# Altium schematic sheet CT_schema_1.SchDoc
size 514 x 469 mm
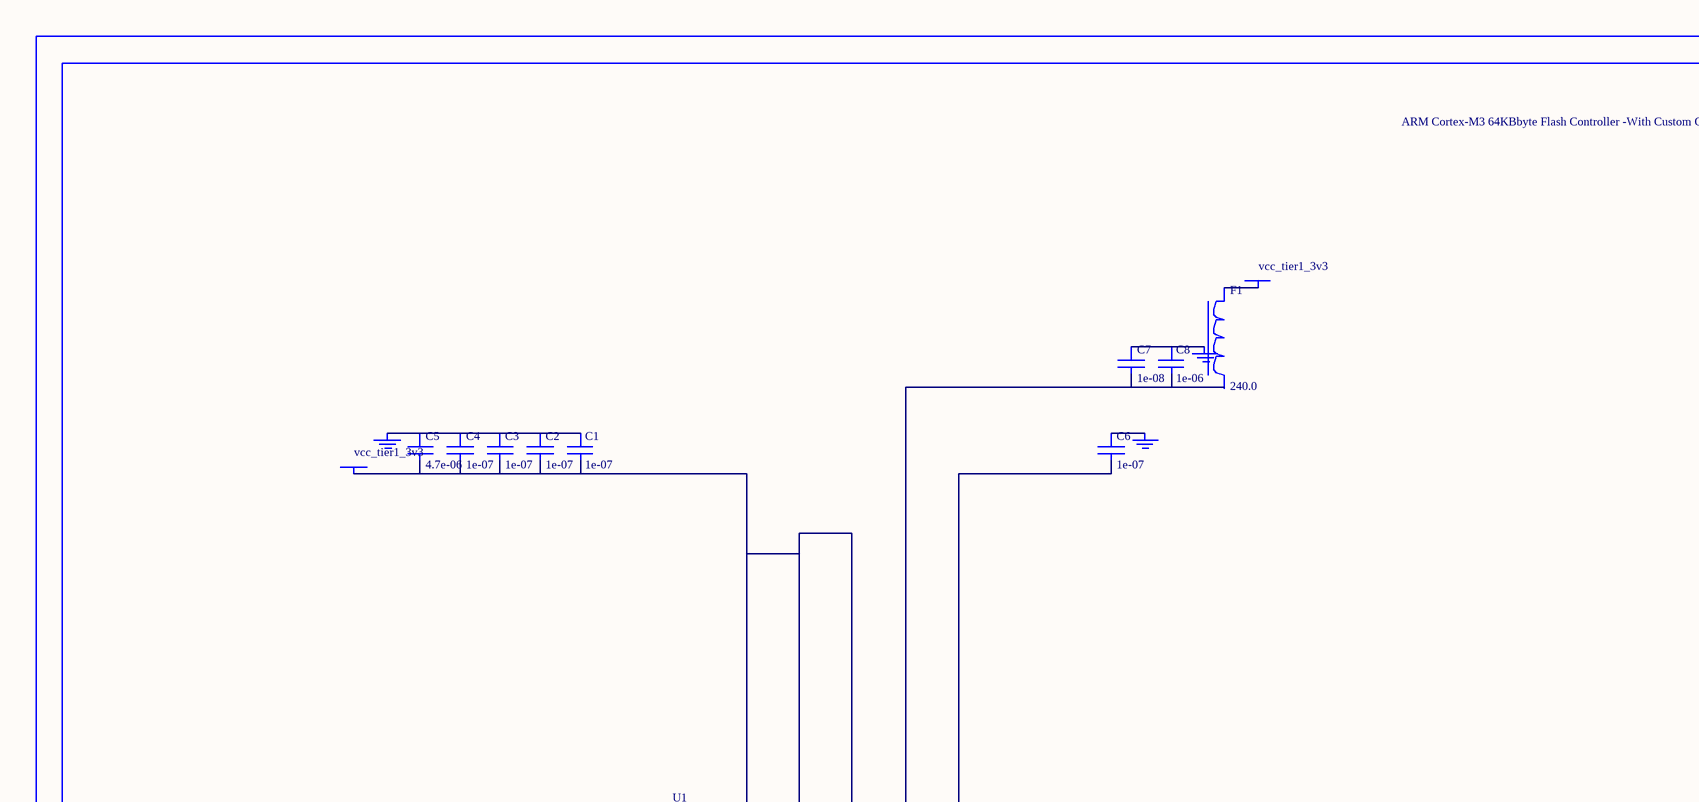
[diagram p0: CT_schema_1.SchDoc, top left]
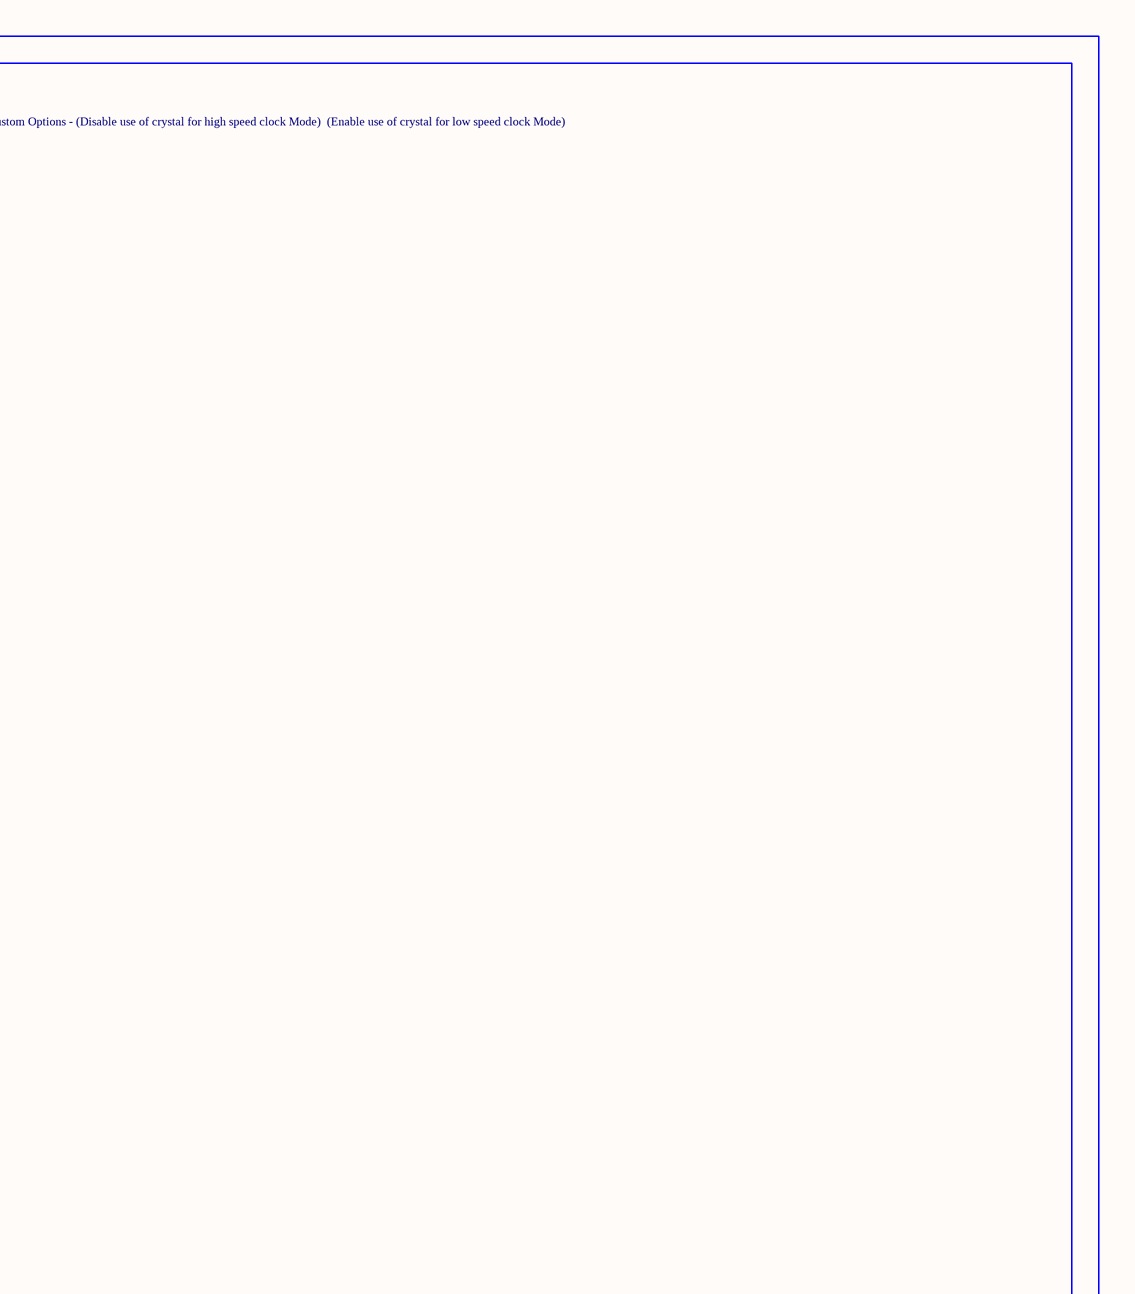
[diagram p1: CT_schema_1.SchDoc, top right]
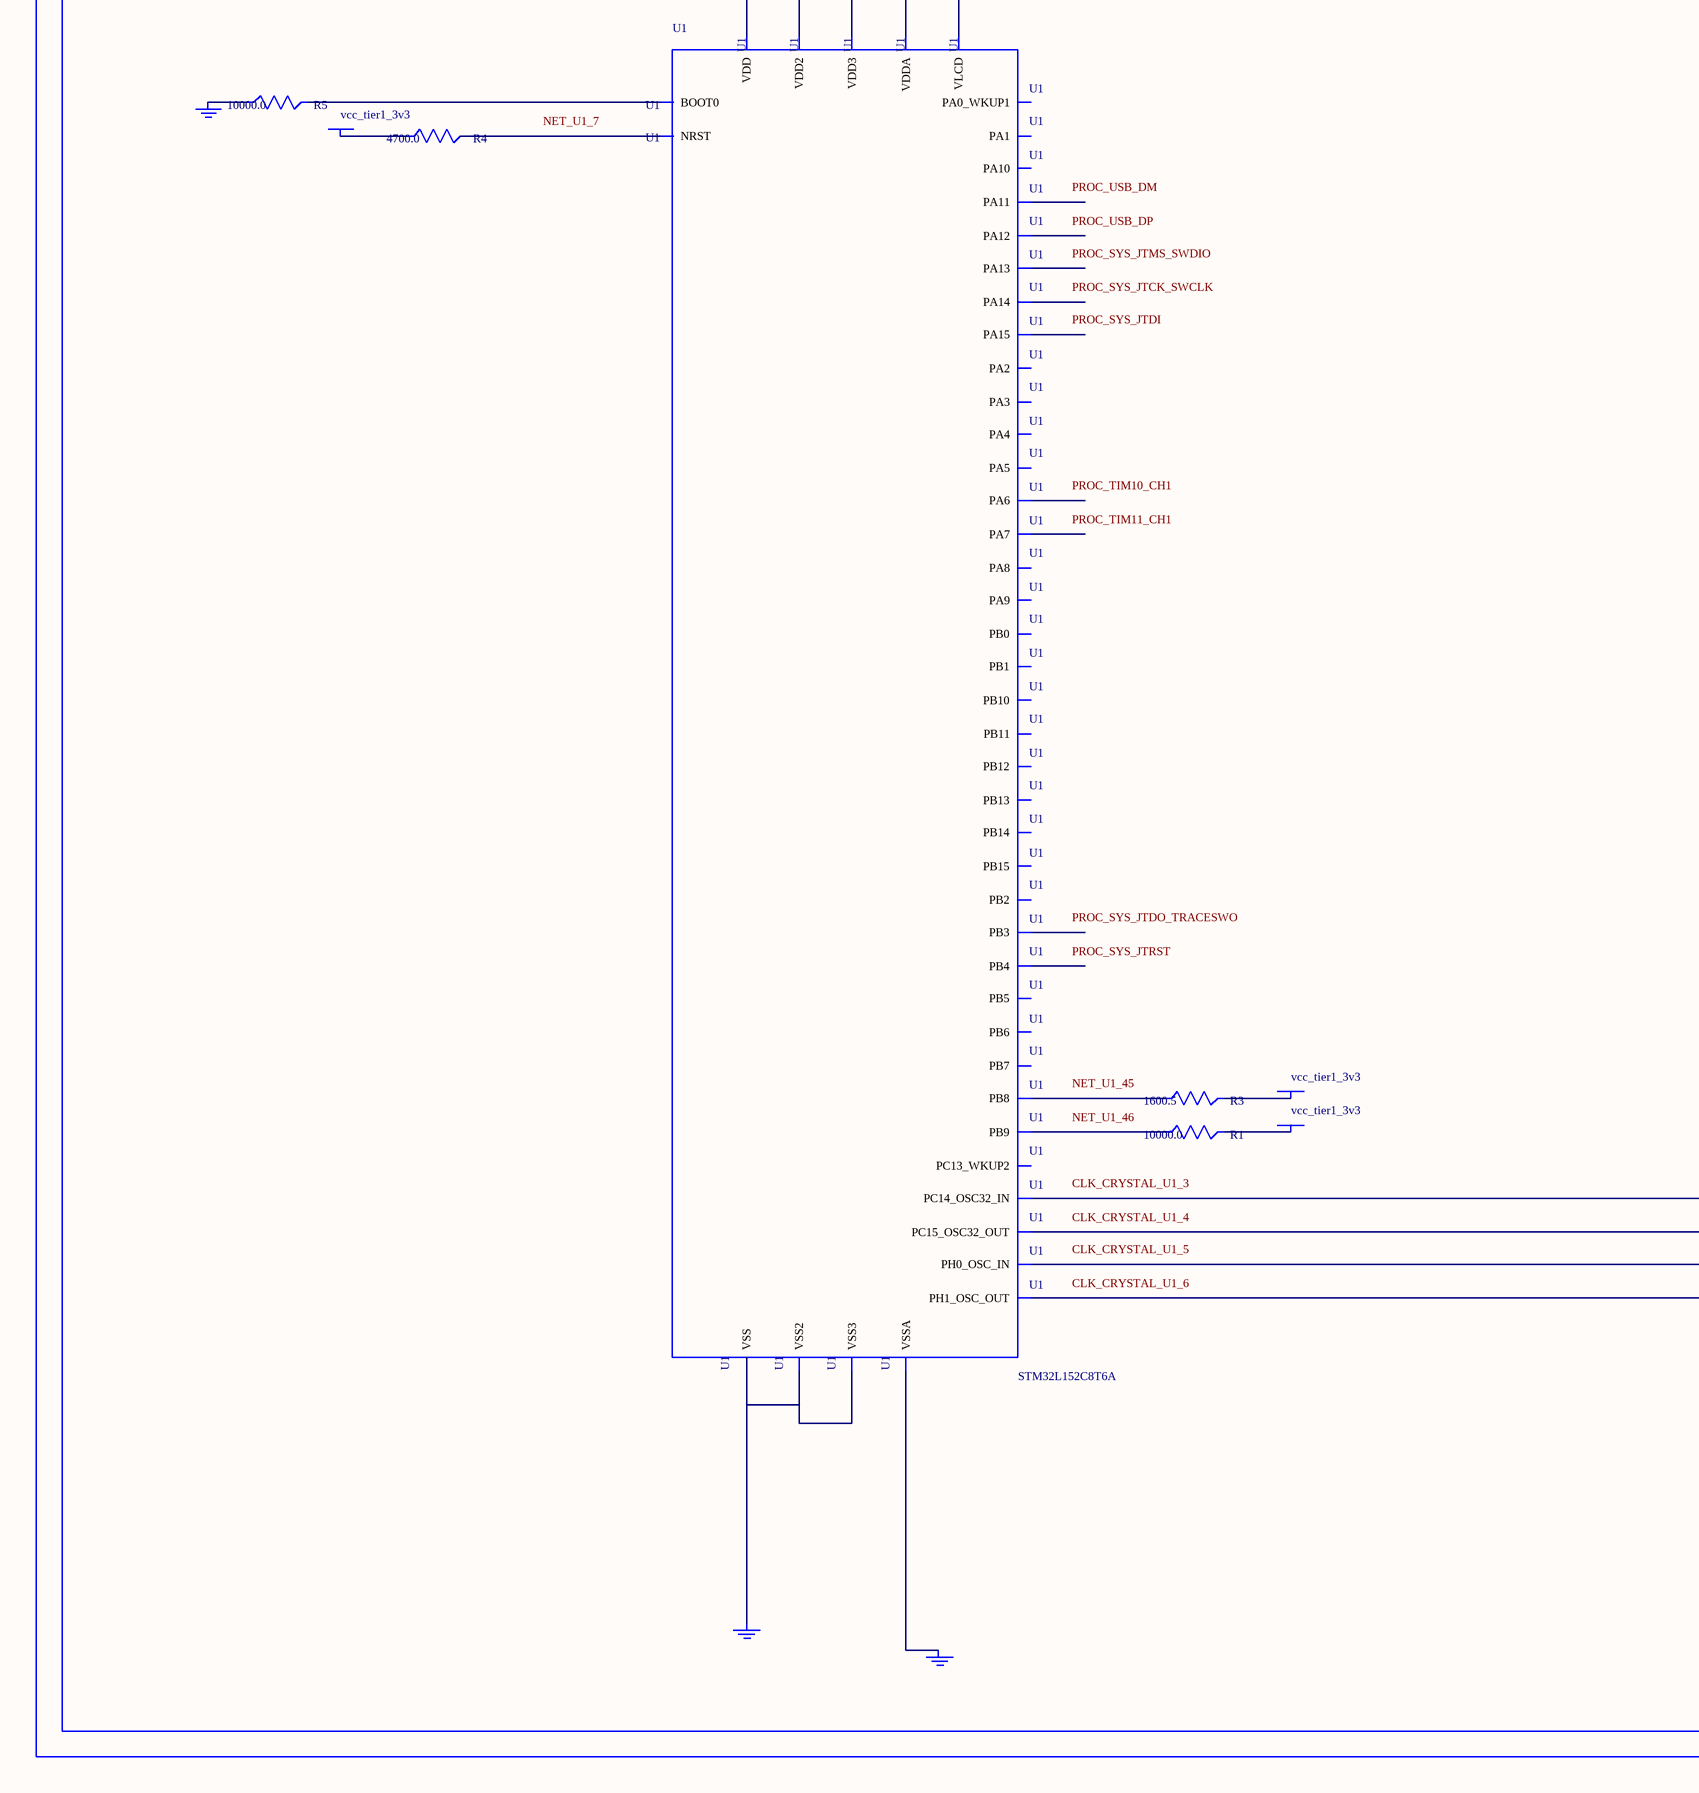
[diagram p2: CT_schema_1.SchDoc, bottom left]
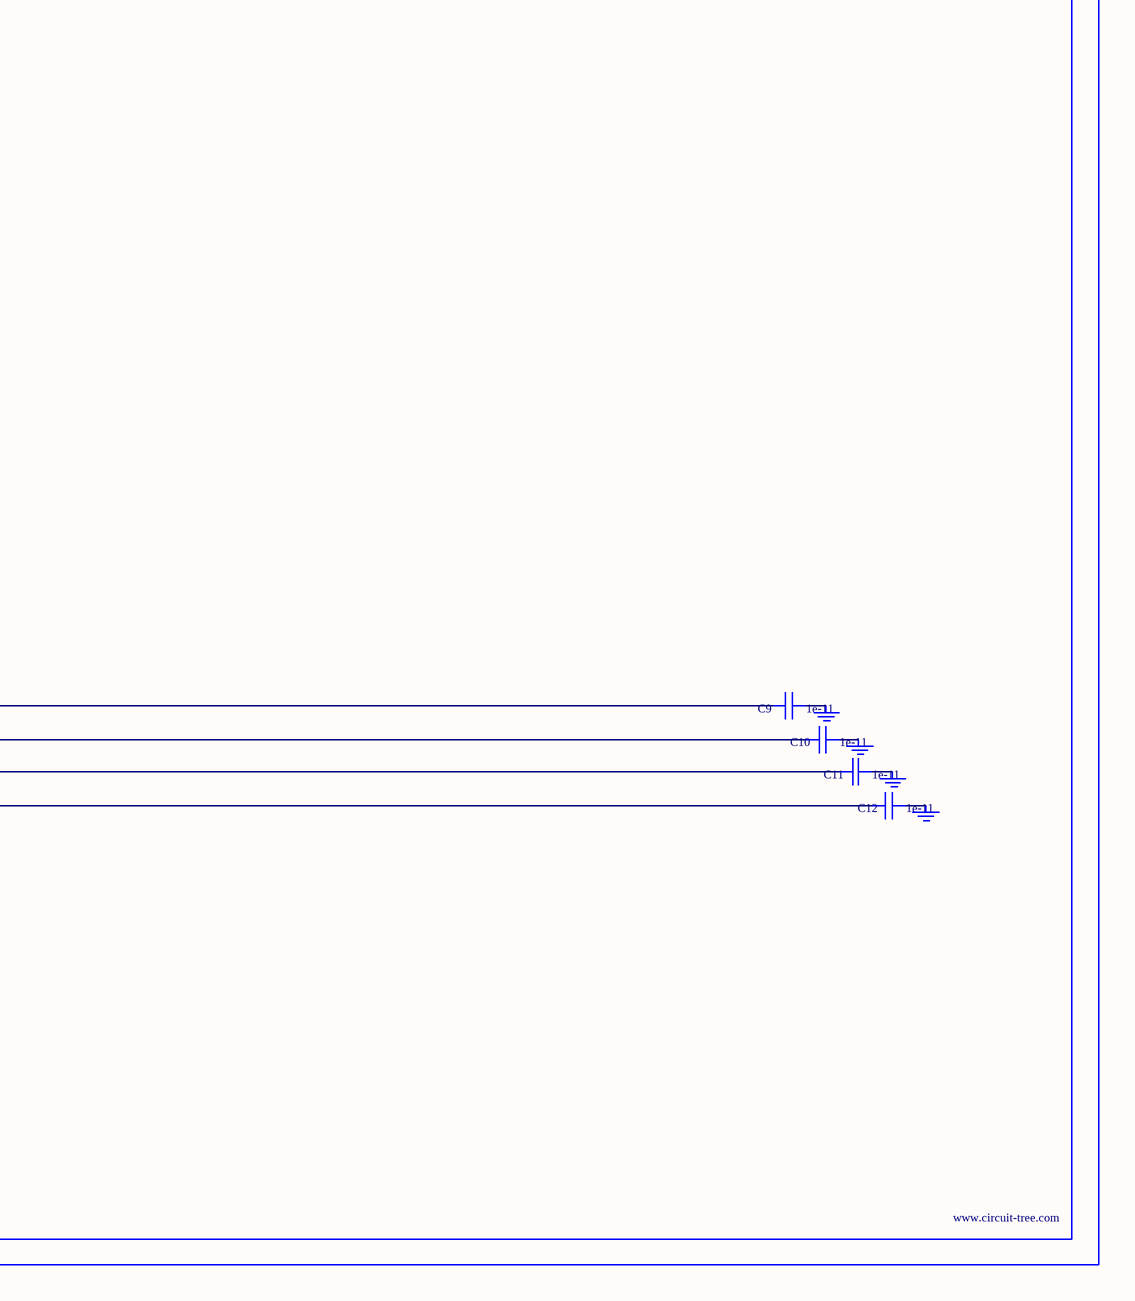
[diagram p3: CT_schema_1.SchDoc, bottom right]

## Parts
BORDER0  (no value)
C1  1e-07  [C0603]
C2  1e-07  [C0603]
C3  1e-07  [C0603]
C4  1e-07  [C0603]
C5  4.7e-06  [C0603]
C6  1e-07  [C0603]
C7  1e-08  [C0603]
C8  1e-06  [C0603]
C9  1e-11  [C0402]
C10  1e-11  [C0402]
C11  1e-11  [C0402]
C12  1e-11  [C0402]
F1  240.0  [L0603]
GND_INSTANCE_0_0  (no value)
GND_INSTANCE_0_1  (no value)
GND_INSTANCE_0_2  (no value)
GND_INSTANCE_0_3  (no value)
GND_INSTANCE_0_4  (no value)
GND_INSTANCE_0_5  (no value)
GND_INSTANCE_0_6  (no value)
GND_INSTANCE_0_7  (no value)
GND_INSTANCE_0_8  (no value)
GND_INSTANCE_0_9  (no value)
POWER_INSTANCE_0_0  vcc_tier1_3v3
POWER_INSTANCE_0_1  vcc_tier1_3v3
POWER_INSTANCE_0_2  vcc_tier1_3v3
POWER_INSTANCE_0_3  vcc_tier1_3v3
POWER_INSTANCE_0_4  vcc_tier1_3v3
R1  10000.0  [R0603]
R3  1600.5  [R0603]
R4  4700.0  [R0603]
R5  10000.0  [R0603]
U1  STM32L152C8T6A  [LQFP48]

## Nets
NetC1_1: C1.1 C2.1 C3.1 C4.1 C5.1 GND_INSTANCE_0_7.0(GND)
NetC1_2: C1.2 C2.2 C3.2 C4.2 C5.2 POWER_INSTANCE_0_1.0(PWR) U1.24(VDD) U1.36(VDD2) U1.48(VDD3)
NetC6_1: C6.1 GND_INSTANCE_0_0.0(GND)
NetC6_2: C6.2 U1.1(VLCD)
NetC7_1: C7.1 C8.1 GND_INSTANCE_0_6.0(GND)
NetC7_2: C7.2 C8.2 U1.9(VDDA)
NetC9_1: C9.1 GND_INSTANCE_0_1.0(GND)
NetC9_2: C9.2 U1.3(PC14_OSC32_IN)
NetC10_1: C10.1 GND_INSTANCE_0_2.0(GND)
NetC10_2: C10.2 U1.4(PC15_OSC32_OUT)
NetC11_1: C11.1 GND_INSTANCE_0_3.0(GND)
NetC11_2: C11.2 U1.5(PH0_OSC_IN)
NetC12_1: C12.1 GND_INSTANCE_0_4.0(GND)
NetC12_2: C12.2 U1.6(PH1_OSC_OUT)
NetF1_1: F1.1 POWER_INSTANCE_0_0.0(PWR)
NetGND_INSTANCE_0_5_0: GND_INSTANCE_0_5.0(GND) U1.8(VSSA)
NetGND_INSTANCE_0_8_0: GND_INSTANCE_0_8.0(GND) R5.1
NetGND_INSTANCE_0_9_0: GND_INSTANCE_0_9.0(GND) U1.23(VSS) U1.35(VSS2) U1.47(VSS3)
NetPOWER_INSTANCE_0_2_0: POWER_INSTANCE_0_2.0(PWR) R4.1
NetPOWER_INSTANCE_0_3_0: POWER_INSTANCE_0_3.0(PWR) R3.2
NetPOWER_INSTANCE_0_4_0: POWER_INSTANCE_0_4.0(PWR) R1.2
NetR1_1: R1.1 U1.46(PB9)
NetR3_1: R3.1 U1.45(PB8)
NetR4_2: R4.2 U1.7(NRST)
NetR5_2: R5.2 U1.44(BOOT0)

Not connected (* = marked no-connect by the designer): F1 2; U1 2(PC13_WKUP2) 10(PA0_WKUP1) 11(PA1) 12(PA2) 13(PA3) 14(PA4) 15(PA5) 16(PA6) 17(PA7) 18(PB0) 19(PB1) 20(PB2) 21(PB10) 22(PB11) 25(PB12) 26(PB13) 27(PB14) 28(PB15) 29(PA8) 30(PA9) 31(PA10) 32(PA11) 33(PA12) 34(PA13) 37(PA14) 38(PA15) 39(PB3) 40(PB4) 41(PB5) 42(PB6) 43(PB7)

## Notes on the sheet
- Labels drawn without touching a wire or pin: CLK_CRYSTAL_U1_3, CLK_CRYSTAL_U1_4, CLK_CRYSTAL_U1_5, CLK_CRYSTAL_U1_6, NET_U1_7, NET_U1_45, NET_U1_46, PROC_SYS_JTCK_SWCLK, PROC_SYS_JTDI, PROC_SYS_JTDO_TRACESWO, PROC_SYS_JTMS_SWDIO, PROC_SYS_JTRST, PROC_TIM10_CH1, PROC_TIM11_CH1, PROC_USB_DM, PROC_USB_DP

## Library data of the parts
BORDER0 = BORDER_PAGE0
C1-C4 C6 = 06035C104K4Z2A
C5 = GRM188R6YA475KE15D
C7 = 06035C103K4Z2A
C8 = C0603C105K3RACTU
C9-C12 = C0402C100K3GACTU
F1 = Z0603C241ASMST
GND_INSTANCE_0_0-GND_INSTANCE_0_9 = GND
POWER_INSTANCE_0_0-POWER_INSTANCE_0_4 = PWR
R1 R5 = RC0603JR-0710KL
R3 = R3
R4 = RC0603JR-074K7L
